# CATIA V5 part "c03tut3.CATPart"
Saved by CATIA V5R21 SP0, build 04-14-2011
Part number: c03tut3
Bounding box of the stored display mesh (mm): x 0 to 0, y -100 to 100, z 0 to 90
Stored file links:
  D:\CATIA V5R21 E-RESOURCES\CATIA-V5R21\catia-v5r21-prt\c03-catia-v5r21-prt\catia-v5r21-tut-03.CATPart
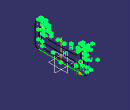
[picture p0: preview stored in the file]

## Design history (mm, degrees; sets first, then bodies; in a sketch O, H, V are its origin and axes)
Body1 (main body)
  Sketch1 on yz-plane, origin (0, 0, 0), H (0, 1, 0), V (0, 0, 1)
    line L1 (0, 0) -> (85, 0)
    line L2 (100, 15) -> (100, 80)
    line L3 (90, 90) -> (70, 90)
    line L4 (60, 80) -> (60, 60)
    line L5 (50, 50) -> (0, 50)
    point P1 (0, 50)
    arc A1 centre (85, 15) radius 15 from (85, 0) to (100, 15) ccw
    point P2 (85, 0)
    point P3 (100, 15)
    arc A2 centre (50, 60) radius 10 from (60, 60) to (50, 50) cw
    point P5 (60, 60)
    point P6 (50, 50)
    arc A3 centre (70, 80) radius 10 from (70, 90) to (60, 80) ccw
    point P8 (70, 90)
    point P9 (60, 80)
    arc A4 centre (90, 80) radius 10 from (100, 80) to (90, 90) ccw
    point P11 (100, 80)
    point P12 (90, 90)
    construction line L6 (80, 70) -> (80, 40)
    line L7 (85, 70) -> (85, 40)
    line L8 (75, 40) -> (75, 70)
    arc A5 centre (80, 40) radius 5 from (85, 40) to (75, 40) cw
    arc A6 centre (80, 70) radius 5 from (75, 70) to (85, 70) cw
    point P16 (85, 70)
    point P17 (85, 40)
    point P18 (75, 40)
    point P19 (75, 70)
    point P20 (0, 0)
    point P21 (0, 50)
    point P22 (-85, 0)
    point P23 (-100, 15)
    point P25 (-60, 60)
    point P26 (-50, 50)
    point P28 (-70, 90)
    point P29 (-60, 80)
    point P31 (-100, 80)
    point P32 (-90, 90)
    construction line L9 (-80, 70) -> (-80, 40)
    point P36 (-85, 70)
    point P37 (-85, 40)
    point P38 (-75, 40)
    point P39 (-75, 70)
    line L10 (0, 0) -> (-85, 0)
    line L11 (-100, 15) -> (-100, 80)
    line L12 (-90, 90) -> (-70, 90)
    line L13 (-60, 80) -> (-60, 60)
    line L14 (-50, 50) -> (0, 50)
    arc A7 centre (-85, 15) radius 15 from (-85, 0) to (-100, 15) cw
    arc A8 centre (-50, 60) radius 10 from (-60, 60) to (-50, 50) ccw
    arc A9 centre (-70, 80) radius 10 from (-70, 90) to (-60, 80) cw
    arc A10 centre (-90, 80) radius 10 from (-100, 80) to (-90, 90) cw
    line L15 (-85, 70) -> (-85, 40)
    line L16 (-75, 40) -> (-75, 70)
    arc A11 centre (-80, 40) radius 5 from (-85, 40) to (-75, 40) ccw
    arc A12 centre (-80, 70) radius 5 from (-75, 70) to (-85, 70) ccw
    construction line L17 (60, 20) -> (-60, 20)
    point P40 (60, 20)
    line L18 (60, 10) -> (-60, 10)
    line L19 (-60, 30) -> (60, 30)
    arc A13 centre (-60, 20) radius 10 from (-60, 10) to (-60, 30) cw
    arc A14 centre (60, 20) radius 10 from (60, 30) to (60, 10) cw
    radius A1 = 15
    radius A2 = 10
    radius A3 = 10
    radius A4 = 10
    distance L6 L7 = 5
    distance L17 L18 = 10
    horizontal: L1 H, L3 H, L5 H, L17 H
    vertical: L2 V, L4 V
    coincidence: P1 V, P40 L4
    tangency: A1 L1, A1 L2, A2 L4, A2 L5, A3 L3, A3 L4, A4 L2, A4 L3, L6 A3, A5 L7, A6 L7, A5 L8, A6 L8, A13 L18, A14 L18, A13 L19, A14 L19
    symmetry: O P20 V, P1 P21 V, P2 P22 V, P3 P23 V, P5 P25 V, P6 P26 V, P8 P28 V, P9 P29 V, P11 P31 V, P12 P32 V, L6 L9 V, P16 P36 V, P17 P37 V, P18 P38 V, P19 P39 V, L1 L10 V, L2 L11 V, L3 L12 V, L4 L13 V, L5 L14 V, A1 A7 V, A2 A8 V, A3 A9 V, A4 A10 V, L7 L15 V, L8 L16 V, A5 A11 V, A6 A12 V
